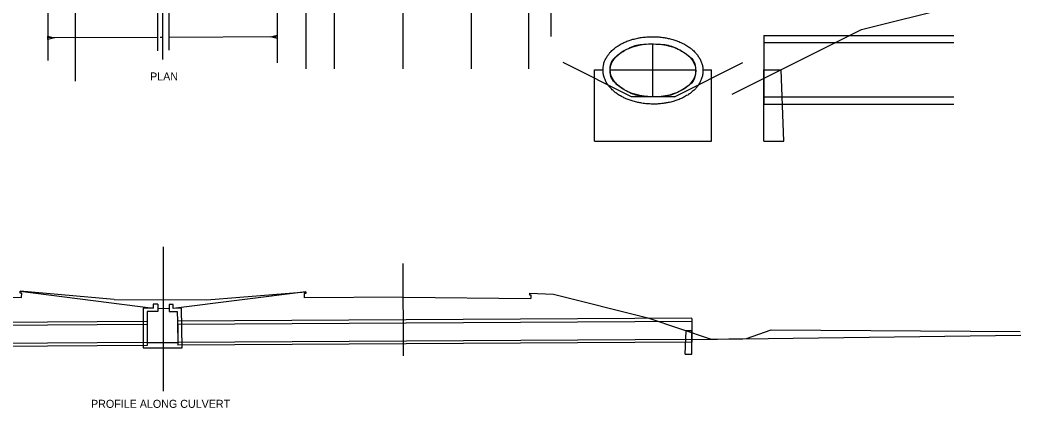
# Model space of a CAD drawing. Extents: x 27863 to 28429, y 1919 to 2120.
# Drawn here: x 28253.7 to 28429, y 1928.4 to 1996.3 of the extents above; entities that cross this region are included whole.
import ezdxf

# ---------------------------------------------------------------- set-up
doc = ezdxf.new("R2010")
doc.units = 0
for name, color, linetype in [('Default', 7, 'Continuous'), ('DR_P_Cells', 7, 'Continuous'), ('DR_P_Culvert', 7, 'Continuous'), ('DR_X_Cells', 7, 'Continuous'), ('DR_X_Culvert', 7, 'Continuous'), ('DR_X_Headwall', 7, 'Continuous'), ('PV_X_EOP', 7, 'Continuous'), ('PV_X_Shoulder', 7, 'Continuous'), ('RD_X_GR_Cable_Bar', 7, 'Continuous'), ('RW_X_CL', 7, 'Continuous'), ('SH_Text', 7, 'Continuous'), ('SV_X_Break_Lines', 7, 'Continuous'), ('SV_X_Toe_of_Slope', 7, 'Continuous'), ('XS_X_Ground_Line', 7, 'Continuous')]:
    doc.layers.add(name, color=color, linetype=linetype)

msp = doc.modelspace()

# ---------------------------------------------------------------- linework, layer by layer
at = {"layer": 'Default'}
for p, q in [((28364.58, 1982.85), (28364.58, 1992.14)), ((28357.08, 1987.6), (28372.07, 1987.6)), ((28277.86, 1945.84), (28279.79, 1945.83))]:
    msp.add_line(p, q, dxfattribs=at)
at = {"layer": 'DR_P_Cells'}
for p, q in [((28275.96, 1943.54), (28275.96, 1939.34)), ((28281.3, 1943.57), (28281.35, 1939.37))]:
    msp.add_line(p, q, dxfattribs=at)
at = {"layer": 'DR_P_Culvert'}
for p, q in [((28384.01, 1992.35), (28417.27, 1992.35)), ((28384.01, 1992.35), (28384.01, 1982.85)), ((28384.01, 1982.85), (28417.27, 1982.85)), ((28371.41, 1943.55), (28281.31, 1943.02)), ((28281.31, 1943.02), (28281.35, 1939.88)), ((28371.4, 1943.55), (28371.4, 1940.41)), ((28275.96, 1942.99), (28176.03, 1942.4)), ((28275.96, 1942.99), (28275.96, 1939.85)), ((28275.96, 1939.85), (28176.03, 1939.26)), ((28371.43, 1940.41), (28281.35, 1939.88))]:
    msp.add_line(p, q, dxfattribs=at)
msp.add_open_spline([(28357.08, 1987.6), (28357.06, 1986.37), (28357.83, 1985.17), (28360.62, 1983.39), (28362.52, 1982.88), (28366.5, 1982.82), (28368.42, 1983.29), (28371.25, 1984.99), (28372.06, 1986.16), (28372.09, 1988.63), (28371.32, 1989.82), (28368.53, 1991.6), (28366.63, 1992.12), (28362.65, 1992.17), (28360.74, 1991.71), (28357.9, 1990), (28357.09, 1988.83), (28357.08, 1987.6)], degree=3, dxfattribs=at)
at = {"layer": 'DR_X_Cells'}
for p, q in [((28277.86, 1946.54), (28277.04, 1946.54)), ((28277.04, 1946.54), (28277.04, 1945.85)), ((28277.86, 1946.54), (28277.86, 1945.31)), ((28280.49, 1946.53), (28279.79, 1946.52)), ((28279.79, 1946.52), (28279.79, 1945.28)), ((28280.51, 1945.83), (28280.49, 1946.53)), ((28277.04, 1945.85), (28275.24, 1945.85)), ((28275.24, 1945.85), (28275.24, 1938.95)), ((28277.86, 1945.31), (28275.96, 1945.31)), ((28275.96, 1945.31), (28275.96, 1943.54)), ((28279.79, 1945.28), (28281.23, 1945.28)), ((28281.98, 1945.85), (28280.51, 1945.83)), ((28281.23, 1945.28), (28281.3, 1943.57)), ((28282.1, 1938.95), (28281.98, 1945.85)), ((28275.96, 1939.85), (28281.35, 1939.88)), ((28275.24, 1938.95), (28282.1, 1938.95))]:
    msp.add_line(p, q, dxfattribs=at)
at = {"layer": 'DR_X_Culvert'}
for p, q in [((28384.01, 1993.6), (28417.27, 1993.6)), ((28384.01, 1993.6), (28384.01, 1981.6)), ((28384.01, 1981.6), (28417.27, 1981.6)), ((28275.96, 1943.54), (28176.03, 1942.95)), ((28371.4, 1944.1), (28281.3, 1943.57)), ((28371.4, 1944.03), (28371.41, 1939.9)), ((28371.41, 1939.9), (28281.35, 1939.37)), ((28275.96, 1939.34), (28176.03, 1938.75))]:
    msp.add_line(p, q, dxfattribs=at)
msp.add_ellipse((28364.58, 1987.5), major_axis=(-7.5, 0.1), ratio=0.619512, dxfattribs=at)
msp.add_open_spline([(28355.83, 1987.62), (28355.82, 1987.4), (28355.84, 1987.18), (28355.9, 1986.74), (28355.95, 1986.53), (28356.08, 1986.11), (28356.16, 1985.91), (28356.35, 1985.51), (28356.45, 1985.32), (28356.82, 1984.76), (28357.11, 1984.42), (28357.77, 1983.78), (28358.14, 1983.49), (28358.97, 1982.97), (28359.41, 1982.74), (28360.33, 1982.34), (28360.82, 1982.17), (28361.82, 1981.9), (28362.34, 1981.8), (28363.41, 1981.65), (28363.95, 1981.61), (28365.04, 1981.59), (28365.59, 1981.62), (28366.65, 1981.74), (28367.18, 1981.83), (28368.19, 1982.07), (28368.68, 1982.23), (28369.61, 1982.6), (28370.06, 1982.82), (28370.9, 1983.32), (28371.28, 1983.6), (28371.96, 1984.21), (28372.26, 1984.55), (28372.64, 1985.1), (28372.75, 1985.29), (28372.95, 1985.68), (28373.03, 1985.88), (28373.17, 1986.29), (28373.23, 1986.5), (28373.3, 1986.94), (28373.32, 1987.16), (28373.33, 1987.6), (28373.32, 1987.82), (28373.25, 1988.25), (28373.2, 1988.47), (28373.07, 1988.88), (28373, 1989.09), (28372.81, 1989.48), (28372.7, 1989.67), (28372.34, 1990.23), (28372.05, 1990.58), (28371.38, 1991.21), (28371.01, 1991.5), (28370.19, 1992.03), (28369.75, 1992.26), (28368.82, 1992.65), (28368.34, 1992.82), (28367.33, 1993.09), (28366.81, 1993.2), (28365.75, 1993.34), (28365.21, 1993.39), (28364.11, 1993.4), (28363.57, 1993.37), (28362.5, 1993.26), (28361.98, 1993.17), (28360.97, 1992.92), (28360.48, 1992.77), (28359.54, 1992.4), (28359.09, 1992.18), (28358.26, 1991.68), (28357.88, 1991.4), (28357.19, 1990.78), (28356.89, 1990.44), (28356.52, 1989.9), (28356.4, 1989.71), (28356.21, 1989.32), (28356.12, 1989.12), (28355.98, 1988.7), (28355.93, 1988.49), (28355.85, 1988.06), (28355.83, 1987.84), (28355.83, 1987.62)], degree=3, dxfattribs=at)
at = {"layer": 'DR_X_Headwall'}
for p, q in [((28354.33, 1987.6), (28355.83, 1987.6)), ((28354.33, 1975.1), (28354.33, 1987.6)), ((28373.32, 1987.6), (28374.83, 1987.6)), ((28374.83, 1975.1), (28374.83, 1987.6)), ((28384.01, 1975.1), (28384.01, 1987.6)), ((28384.01, 1987.6), (28387.01, 1987.6)), ((28387.51, 1975.1), (28387.01, 1987.6)), ((28354.33, 1975.1), (28374.83, 1975.1)), ((28384.01, 1975.1), (28387.51, 1975.1)), ((28370.23, 1937.82), (28370.4, 1941.91)), ((28371.4, 1941.91), (28370.4, 1941.91)), ((28371.4, 1937.82), (28371.4, 1941.91)), ((28370.23, 1937.82), (28371.4, 1937.82))]:
    msp.add_line(p, q, dxfattribs=at)
at = {"layer": 'PV_X_EOP'}
for p, q in [((28308.68, 2095.84), (28308.75, 1987.75)), ((28332.68, 2095.86), (28332.75, 1987.76)), ((28253.7, 1948.47), (28253.7, 1948.84)), ((28253.98, 1948.47), (28253.7, 1948.47)), ((28253.97, 1947.71), (28253.98, 1948.47)), ((28303.76, 1948.46), (28303.47, 1948.46)), ((28303.47, 1948.46), (28303.47, 1947.66)), ((28303.76, 1948.75), (28303.76, 1948.46)), ((28342.96, 1948.49), (28342.96, 1948.23)), ((28236.6, 1947.94), (28253.97, 1947.71)), ((28320.83, 1947.82), (28303.47, 1947.66)), ((28320.83, 1947.82), (28343.15, 1947.58)), ((28342.96, 1948.23), (28343.15, 1948.23)), ((28343.15, 1948.23), (28343.15, 1947.58))]:
    msp.add_line(p, q, dxfattribs=at)
at = {"layer": 'PV_X_Shoulder'}
for p, q in [((28342.67, 2117.4), (28342.75, 1987.77)), ((28303.68, 2095.84), (28303.75, 1987.75))]:
    msp.add_line(p, q, dxfattribs=at)
at = {"layer": 'RD_X_GR_Cable_Bar'}
msp.add_line((28263.37, 2091.7), (28263.37, 1985.59), dxfattribs=at)
at = {"layer": 'RW_X_CL'}
for p, q in [((28278.69, 1989.4), (28278.66, 2098.84)), ((28320.68, 2098.86), (28320.75, 1987.76)), ((28278.69, 1993.26), (28278.25, 1993.26)), ((28278.74, 1956.58), (28278.77, 1931.31)), ((28320.88, 1937.51), (28320.81, 1953.68))]:
    msp.add_line(p, q, dxfattribs=at)
at = {"layer": 'SV_X_Break_Lines'}
for p, q in [((28298.58, 2091.82), (28298.76, 1988.84)), ((28258.67, 2081.82), (28258.54, 1989.22)), ((28277.78, 1993.27), (28258.54, 1993.18)), ((28298.75, 1993.37), (28279.78, 1993.28))]:
    msp.add_line(p, q, dxfattribs=at)
msp.add_lwpolyline([(28344.3, 2117.45), (28344.39, 2106.94), (28344.41, 2105.34), (28344.82, 2096.41), (28345.78, 2078.24), (28346.45, 2065.67), (28346.58, 2063.21), (28346.58, 2044.48), (28346.7, 1993.45)], dxfattribs=at)
for points in [[(28258.54, 1993.47), (28259.74, 1993.2), (28258.55, 1992.9)], [(28298.76, 1993.09), (28297.56, 1993.36), (28298.75, 1993.66)]]:
    msp.add_lwpolyline(points, close=True, dxfattribs=at)
at = {"layer": 'SV_X_Toe_of_Slope'}
for p, q in [((28277.68, 2031.9), (28277.79, 1990.94)), ((28279.76, 2031.96), (28279.78, 1991.05))]:
    msp.add_line(p, q, dxfattribs=at)
at = {"layer": 'XS_X_Ground_Line'}
for p, q in [((28401.09, 1994.64), (28417.3, 1998.69)), ((28378.43, 1983.31), (28401.09, 1994.64)), ((28360.83, 1982.85), (28348.83, 1988.85)), ((28368.33, 1982.85), (28380.33, 1988.85)), ((28368.33, 1982.85), (28360.83, 1982.85)), ((28253.7, 1948.84), (28277.04, 1945.85)), ((28270.21, 1947.41), (28253.7, 1948.84)), ((28303.76, 1948.75), (28280.51, 1945.83)), ((28286.44, 1947.32), (28303.76, 1948.75)), ((28342.96, 1948.49), (28347.14, 1948.34)), ((28347.14, 1948.34), (28363.66, 1944.15)), ((28270.21, 1947.41), (28286.44, 1947.32)), ((28363.66, 1944.15), (28374.77, 1940.46)), ((28380.97, 1940.53), (28385.26, 1942.07)), ((28385.26, 1942.07), (28428.93, 1941.79)), ((28371.43, 1940.41), (28429.05, 1941.14)), ((28374.77, 1940.46), (28380.97, 1940.53))]:
    msp.add_line(p, q, dxfattribs=at)

# ---------------------------------------------------------------- texts
at = {"layer": 'SH_Text'}
for s, height, p in [('PLAN', 1.402, (28276.47, 1985.73)), ('PROFILE ALONG CULVERT', 1.4019, (28266.13, 1928.42))]:
    msp.add_text(s, height=height, dxfattribs=at).set_placement(p)

doc.saveas('drawing.dxf')
